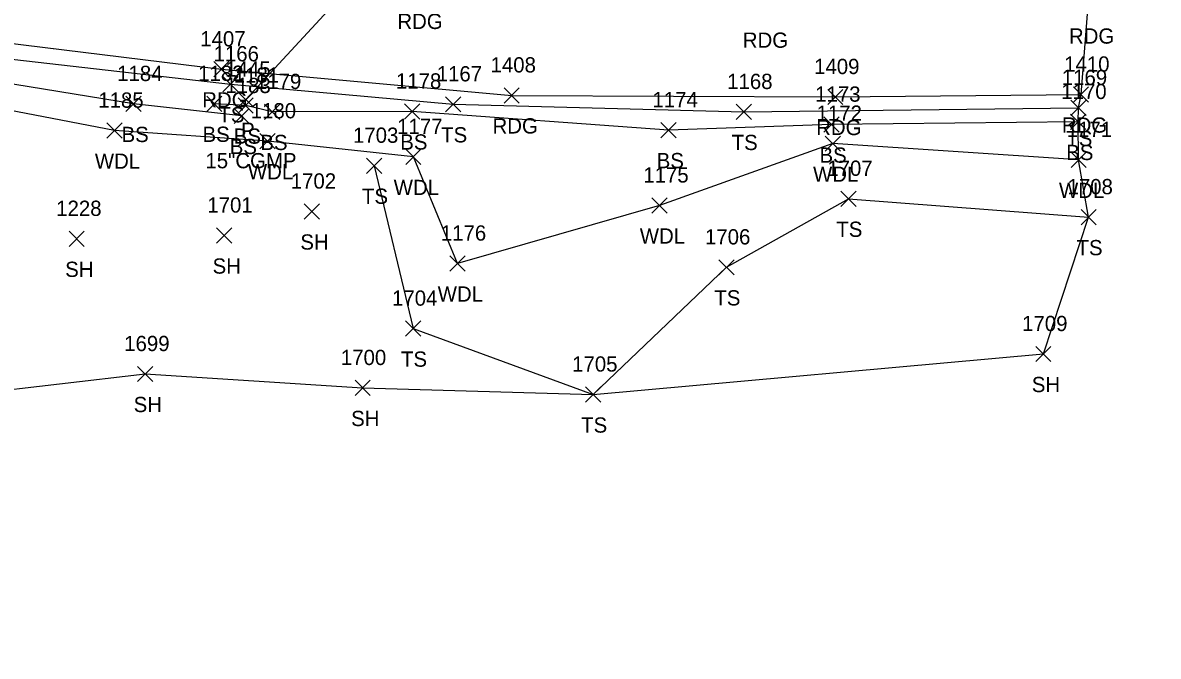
# Model space of a CAD drawing. Extents: x 1633660 to 1636532, y 388643 to 392631.
# Drawn here: x 1634075.1 to 1634224, y 388650.9 to 388733.9 of the extents above; entities that cross this region are included whole.
import ezdxf

# ---------------------------------------------------------------- set-up
doc = ezdxf.new("R2010")
doc.units = 0
for name, color, linetype in [('D_A', 7, 'Continuous'), ('D_C', 7, 'Continuous'), ('D_I', 7, 'Continuous'), ('D_TIC', 7, 'Continuous'), ('DCP', 7, 'Continuous'), ('L_A', 7, 'Continuous'), ('L_I', 7, 'Continuous'), ('L_TIC', 7, 'Continuous'), ('LAWA', 7, 'Continuous'), ('LELB', 7, 'Continuous'), ('LSOGP', 7, 'Continuous'), ('P_A', 7, 'Continuous'), ('P_I', 7, 'Continuous'), ('P_TIC', 7, 'Continuous'), ('PEU', 7, 'Continuous')]:
    doc.layers.add(name, color=color, linetype=linetype)

msp = doc.modelspace()

# ---------------------------------------------------------------- linework, layer by layer
at = {"layer": 'D_TIC'}
for points in [[(1634103.33, 388722.83), (1634105.33, 388724.83)], [(1634105.33, 388722.83), (1634103.33, 388724.83)]]:
    msp.add_lwpolyline(points, dxfattribs=at)
at = {"layer": 'DCP'}
msp.add_lwpolyline([(1634104.33, 388723.83), (1634124.85, 388746.04)], dxfattribs=at)
at = {"layer": 'L_TIC'}
for points in [[(1634101.32, 388724.85), (1634103.32, 388726.85)], [(1634103.32, 388724.85), (1634101.32, 388726.85)], [(1634088.59, 388722.27), (1634090.59, 388724.27)], [(1634090.59, 388722.27), (1634088.59, 388724.27)], [(1634099.2, 388722.29), (1634101.2, 388724.29)], [(1634101.2, 388722.29), (1634099.2, 388724.29)], [(1634103.31, 388722.05), (1634105.31, 388724.05)], [(1634105.31, 388722.05), (1634103.31, 388724.05)], [(1634130.53, 388722.22), (1634132.53, 388724.22)], [(1634132.53, 388722.22), (1634130.53, 388724.22)], [(1634212.51, 388721.74), (1634214.51, 388723.74)], [(1634214.51, 388721.74), (1634212.51, 388723.74)], [(1634102.78, 388720.69), (1634104.78, 388722.69)], [(1634104.78, 388720.69), (1634102.78, 388722.69)], [(1634106.79, 388721.22), (1634108.79, 388723.22)], [(1634108.79, 388721.22), (1634106.79, 388723.22)], [(1634125.13, 388721.28), (1634127.13, 388723.28)], [(1634127.13, 388721.28), (1634125.13, 388723.28)], [(1634168.63, 388721.22), (1634170.63, 388723.22)], [(1634170.63, 388721.22), (1634168.63, 388723.22)], [(1634086.11, 388718.77), (1634088.11, 388720.77)], [(1634088.11, 388718.77), (1634086.11, 388720.77)], [(1634158.77, 388718.84), (1634160.77, 388720.84)], [(1634160.77, 388718.84), (1634158.77, 388720.84)], [(1634180.12, 388719.56), (1634182.12, 388721.56)], [(1634182.12, 388719.56), (1634180.12, 388721.56)], [(1634212.47, 388719.91), (1634214.47, 388721.91)], [(1634214.47, 388719.91), (1634212.47, 388721.91)], [(1634106.18, 388717.38), (1634108.18, 388719.38)], [(1634108.18, 388717.38), (1634106.18, 388719.38)], [(1634180.29, 388717.06), (1634182.29, 388719.06)], [(1634182.29, 388717.06), (1634180.29, 388719.06)], [(1634120.15, 388714.17), (1634122.15, 388716.17)], [(1634122.15, 388714.17), (1634120.15, 388716.17)], [(1634125.3, 388715.32), (1634127.3, 388717.32)], [(1634127.3, 388715.32), (1634125.3, 388717.32)], [(1634212.54, 388714.93), (1634214.54, 388716.93)], [(1634214.54, 388714.93), (1634212.54, 388716.93)], [(1634182.35, 388709.84), (1634184.35, 388711.84)], [(1634184.35, 388709.84), (1634182.35, 388711.84)], [(1634157.57, 388708.96), (1634159.57, 388710.96)], [(1634159.57, 388708.96), (1634157.57, 388710.96)], [(1634112, 388708.17), (1634114, 388710.17)], [(1634114, 388708.17), (1634112, 388710.17)], [(1634213.85, 388707.43), (1634215.85, 388709.43)], [(1634215.85, 388707.43), (1634213.85, 388709.43)], [(1634081.15, 388704.59), (1634083.15, 388706.59)], [(1634083.15, 388704.59), (1634081.15, 388706.59)], [(1634100.48, 388705.02), (1634102.48, 388707.02)], [(1634102.48, 388705.02), (1634100.48, 388707.02)], [(1634131.08, 388701.35), (1634133.08, 388703.35)], [(1634133.08, 388701.35), (1634131.08, 388703.35)], [(1634166.36, 388700.85), (1634168.36, 388702.85)], [(1634168.36, 388700.85), (1634166.36, 388702.85)], [(1634125.27, 388692.82), (1634127.27, 388694.82)], [(1634127.27, 388692.82), (1634125.27, 388694.82)], [(1634207.91, 388689.49), (1634209.91, 388691.49)], [(1634209.91, 388689.49), (1634207.91, 388691.49)], [(1634090.13, 388686.87), (1634092.13, 388688.87)], [(1634092.13, 388686.87), (1634090.13, 388688.87)], [(1634118.65, 388685.04), (1634120.65, 388687.04)], [(1634120.65, 388685.04), (1634118.65, 388687.04)], [(1634148.89, 388684.18), (1634150.89, 388686.18)], [(1634150.89, 388684.18), (1634148.89, 388686.18)]]:
    msp.add_lwpolyline(points, dxfattribs=at)
at = {"layer": 'LAWA'}
msp.add_lwpolyline([(1634213.54, 388715.93), (1634181.29, 388718.06), (1634158.57, 388709.96), (1634132.08, 388702.35), (1634126.3, 388716.32), (1634107.18, 388718.38), (1634087.11, 388719.77), (1634044.14, 388728.03), (1634007.74, 388730.58), (1633979.24, 388736.34), (1633973.65, 388737.75)], dxfattribs=at)
at = {"layer": 'LELB'}
for points in [[(1633929.25, 388734.22), (1633932.64, 388741.33), (1633934.84, 388748.14), (1633955.61, 388748.95), (1633990.07, 388745.5), (1634019.59, 388737.41), (1634056.05, 388731.14), (1634102.32, 388725.85), (1634131.53, 388723.22), (1634169.63, 388722.22), (1634213.51, 388722.74)], [(1634103.78, 388721.69), (1634089.59, 388723.27), (1634044.5, 388730.63), (1634008.78, 388736.74), (1633974.13, 388741.19), (1633971.98, 388741.19), (1633967.26, 388742.03), (1633963.35, 388743.2), (1633950.4, 388742.79), (1633939.89, 388743.26), (1633938.77, 388738.1), (1633951.99, 388740.33), (1633960.06, 388738.71)], [(1634213.47, 388720.91), (1634181.12, 388720.56), (1634159.77, 388719.84), (1634126.13, 388722.28), (1634107.79, 388722.22), (1634104.31, 388723.05), (1634100.2, 388723.29)], [(1634121.15, 388715.17), (1634126.27, 388693.82), (1634149.89, 388685.18), (1634167.36, 388701.85), (1634183.35, 388710.84), (1634214.85, 388708.43)]]:
    msp.add_lwpolyline(points, dxfattribs=at)
at = {"layer": 'LSOGP'}
msp.add_lwpolyline([(1633892.15, 388670.64), (1633924.06, 388658.35), (1633934.83, 388655.28), (1633940.09, 388658.82), (1633943.21, 388657.8), (1633944.44, 388650.87), (1634007.22, 388659.11), (1634047.38, 388665.25), (1634068.61, 388685.27), (1634091.13, 388687.87), (1634119.65, 388686.04), (1634149.89, 388685.18), (1634208.91, 388690.49), (1634214.85, 388708.43), (1634213.54, 388715.93), (1634213.47, 388720.91), (1634213.51, 388722.74), (1634213.85, 388724.5), (1634214.78, 388736.17), (1634218.98, 388740.85), (1634254.67, 388740.24)], dxfattribs=at)
at = {"layer": 'P_TIC'}
for points in [[(1634100.12, 388726.81), (1634102.12, 388728.81)], [(1634102.12, 388726.81), (1634100.12, 388728.81)], [(1634138.19, 388723.39), (1634140.19, 388725.39)], [(1634140.19, 388723.39), (1634138.19, 388725.39)], [(1634180.63, 388723.18), (1634182.63, 388725.18)], [(1634182.63, 388723.18), (1634180.63, 388725.18)], [(1634212.85, 388723.5), (1634214.85, 388725.5)], [(1634214.85, 388723.5), (1634212.85, 388725.5)]]:
    msp.add_lwpolyline(points, dxfattribs=at)
at = {"layer": 'PEU'}
msp.add_lwpolyline([(1633965.07, 388753.44), (1633990.25, 388749.16), (1634020.6, 388740.58), (1634057, 388733.24), (1634101.12, 388727.81), (1634139.19, 388724.39), (1634181.63, 388724.18), (1634213.85, 388724.5)], dxfattribs=at)

# ---------------------------------------------------------------- texts
at = {"layer": 'D_A'}
msp.add_text('P', height=2, dxfattribs=at).set_placement((1634103.7, 388718.83))
at = {"layer": 'D_C'}
msp.add_text('15"CGMP', height=2, dxfattribs=at).set_placement((1634099.03, 388714.83))
at = {"layer": 'D_I'}
msp.add_text('1445', height=2, dxfattribs=at).set_placement((1634101.63, 388726.83))
at = {"layer": 'L_A'}
for s, p in [('TS', (1634100.73, 388720.85)), ('BS', (1634088.03, 388718.27)), ('BS', (1634098.65, 388718.29)), ('BS', (1634102.75, 388718.05)), ('BS', (1634106.23, 388717.22)), ('BS', (1634124.58, 388717.28)), ('TS', (1634129.94, 388718.22)), ('TS', (1634168.04, 388717.22)), ('TS', (1634211.92, 388717.74)), ('BS', (1634102.22, 388716.69)), ('BS', (1634211.91, 388715.91)), ('WDL', (1634084.53, 388714.77)), ('BS', (1634158.21, 388714.84)), ('BS', (1634179.56, 388715.56)), ('WDL', (1634104.6, 388713.38)), ('WDL', (1634178.71, 388713.06)), ('WDL', (1634123.72, 388711.32)), ('TS', (1634119.56, 388710.17)), ('WDL', (1634210.96, 388710.93)), ('TS', (1634181.76, 388705.84)), ('SH', (1634111.48, 388704.17)), ('WDL', (1634155.99, 388704.96)), ('TS', (1634213.26, 388703.43)), ('SH', (1634099.97, 388701.02)), ('SH', (1634080.64, 388700.59)), ('WDL', (1634129.49, 388697.35)), ('TS', (1634165.77, 388696.85)), ('TS', (1634124.68, 388688.82)), ('SH', (1634207.4, 388685.49)), ('SH', (1634089.62, 388682.87)), ('SH', (1634118.14, 388681.04)), ('TS', (1634148.3, 388680.18))]:
    msp.add_text(s, height=2, dxfattribs=at).set_placement(p)
at = {"layer": 'L_I'}
for s, p in [('1166', (1634100.1, 388728.85)), ('1184', (1634087.46, 388726.27)), ('1182', (1634098.08, 388726.29)), ('1181', (1634102.75, 388726.05)), ('1167', (1634129.36, 388726.22)), ('1183', (1634101.65, 388724.69)), ('1179', (1634105.65, 388725.22)), ('1178', (1634124.01, 388725.28)), ('1168', (1634167.45, 388725.22)), ('1169', (1634211.33, 388725.74)), ('1173', (1634178.99, 388723.56)), ('1170', (1634211.26, 388723.91)), ('1185', (1634084.98, 388722.77)), ('1174', (1634157.65, 388722.84)), ('1180', (1634104.97, 388721.38)), ('1172', (1634179.17, 388721.06)), ('1177', (1634124.17, 388719.32)), ('1171', (1634211.98, 388718.93)), ('1703', (1634118.38, 388718.17)), ('1175', (1634156.45, 388712.96)), ('1707', (1634180.58, 388713.84)), ('1702', (1634110.22, 388712.17)), ('1708', (1634212.08, 388711.43)), ('1228', (1634079.46, 388708.59)), ('1701', (1634099.28, 388709.02)), ('1176', (1634129.9, 388705.35)), ('1706', (1634164.54, 388704.85)), ('1704', (1634123.5, 388696.82)), ('1709', (1634206.13, 388693.49)), ('1699', (1634088.38, 388690.87)), ('1700', (1634116.79, 388689.04)), ('1705', (1634147.12, 388688.18))]:
    msp.add_text(s, height=2, dxfattribs=at).set_placement(p)
at = {"layer": 'P_A'}
for p in [(1634124.2, 388733.09), (1634169.5, 388730.63), (1634212.27, 388731.17), (1634098.61, 388722.81), (1634136.68, 388719.39), (1634179.12, 388719.18), (1634211.34, 388719.5)]:
    msp.add_text('RDG', height=2, dxfattribs=at).set_placement(p)
at = {"layer": 'P_I'}
for s, p in [('1407', (1634098.35, 388730.81)), ('1408', (1634136.42, 388727.39)), ('1409', (1634178.85, 388727.18)), ('1410', (1634211.64, 388727.5))]:
    msp.add_text(s, height=2, dxfattribs=at).set_placement(p)

doc.saveas('drawing.dxf')
